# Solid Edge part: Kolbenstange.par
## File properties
Username: bmolnar
Dokumentum tartalom típus: 0
Author: bmolnar
Last saved by: bmolnar
Revision: 102
Sűrűség: 0,000 kg/m^3
Pontosság: 0,990
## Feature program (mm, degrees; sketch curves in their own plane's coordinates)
base feature "unnamed BaseFeature 1"
thread "unnamed Thread 1"
chamfer "Letörés_1"  SetBackValue2 = 20 deg
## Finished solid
Body 1: solid body, 21 faces, 32 edges, 14 vertices.
  Faces by surface: plane 8, cylinder 5, cone 4, torus 4
  Edges by curve: circle 17, line 9, curve on surface 4, ellipse 2
Bounding box of the edges (mm; curved faces can reach further): 50.000 x 50.000 x 1644.000, from (-25, -25, -86.5) to (25, 25, 1557.5).
Cylindrical faces by radius (mm): R6.75 x1, R8 x1, R9.75 x1, R10 x1, R25 x1
Conical faces (half-angle, radius in mm at the cone's reference point): 20 deg R8 x1, 30 deg R9.875 x1, 45 deg R24.25 x1, 60 deg R7.375 x1
Toroidal faces (ring radius, tube radius in mm): R7.15 r0.4 x2, R8.55 r1.2 x2
Planar faces by outward normal: +x 1, +z 3, -x 1, -z 1, oblique 2
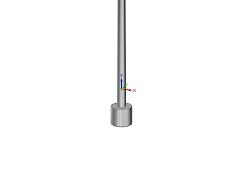
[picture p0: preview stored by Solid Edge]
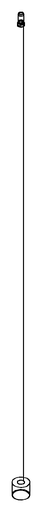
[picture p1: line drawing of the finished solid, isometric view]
